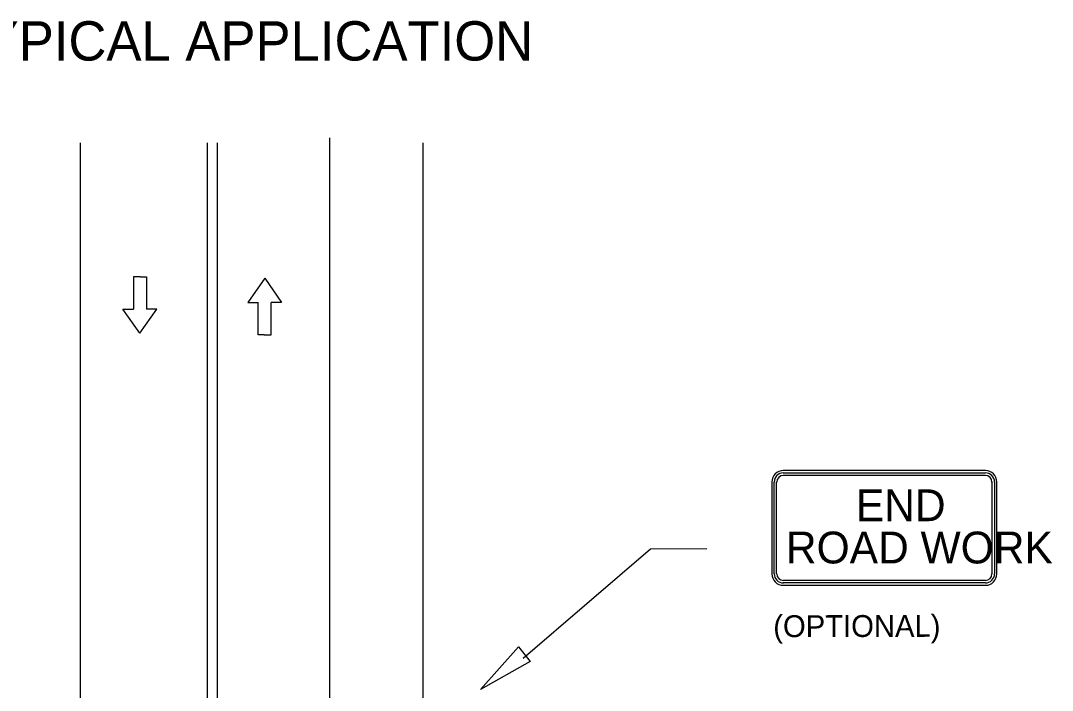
# Model space of a CAD drawing. Extents: x 1531.35 to 1538.58, y 1529.59 to 1539.23.
# Drawn here: x 1535.338 to 1538.171, y 1537.39 to 1539.228 of the extents above; entities that cross this region are included whole.
import ezdxf

# ---------------------------------------------------------------- set-up
doc = ezdxf.new("R2010")
doc.units = 0
for name, color, linetype in [('DETL-DIMS', 7, 'Continuous'), ('DETL-LINE', 7, 'Continuous'), ('DETL-NOTE', 7, 'Continuous'), ('DETL-TITL', 7, 'Continuous'), ('USER-BORD', 7, 'Continuous')]:
    doc.layers.add(name, color=color, linetype=linetype)

# ---------------------------------------------------------------- blocks, each defined once
blk = doc.blocks.new('TD')
at = {"layer": 'USER-BORD'}
for p, q in [((0, 0), (-0.0539, -0.077)), ((0, 0), (0.0539, -0.077)), ((-0.0539, -0.077), (-0.0208, -0.077)), ((-0.0208, -0.1803), (-0.0208, -0.077)), ((0.0208, -0.1803), (0.0208, -0.077)), ((0.0539, -0.077), (0.0208, -0.077)), ((-0.0017, -0.1803), (-0.0208, -0.1803)), ((-0.0017, -0.1803), (0.0017, -0.1803)), ((0.0017, -0.1803), (0.0208, -0.1803))]:
    blk.add_line(p, q, dxfattribs=at)

msp = doc.modelspace()

# ---------------------------------------------------------------- linework, layer by layer
at = {"layer": 'DETL-DIMS'}
for p, q in [((1536.7178, 1537.4779), (1537.0678, 1537.7784)), ((1537.0678, 1537.7784), (1537.2224, 1537.7787))]:
    msp.add_line(p, q, dxfattribs=at)
msp.add_lwpolyline([(1536.7049, 1537.5091), (1536.7372, 1537.4689), (1536.6003, 1537.3919)], close=True, dxfattribs=at)
at = {"layer": 'DETL-LINE'}
for p, q in [((1535.5016, 1538.8924), (1535.5016, 1531.7496)), ((1535.8503, 1538.8924), (1535.8503, 1531.7496)), ((1535.8772, 1538.8924), (1535.8772, 1531.7496)), ((1536.1857, 1538.9058), (1536.1857, 1535.6352)), ((1536.4426, 1538.8924), (1536.4426, 1531.7496)), ((1537.9869, 1537.993), (1537.4322, 1537.993)), ((1537.4322, 1537.9866), (1537.9869, 1537.9866)), ((1537.4008, 1537.9616), (1537.4008, 1537.7094)), ((1537.4072, 1537.7094), (1537.4072, 1537.9616)), ((1537.4139, 1537.7094), (1537.4139, 1537.9616)), ((1537.4322, 1537.9799), (1537.9869, 1537.9799)), ((1538.0049, 1537.9616), (1538.0049, 1537.7094)), ((1538.005, 1537.9614), (1538.0049, 1537.9616)), ((1538.0122, 1537.9616), (1538.0122, 1537.7094)), ((1538.0186, 1537.7094), (1538.0186, 1537.9616)), ((1537.9869, 1537.6914), (1537.4322, 1537.6914)), ((1537.9869, 1537.6842), (1537.4322, 1537.6842)), ((1537.4322, 1537.6778), (1537.9869, 1537.6778))]:
    msp.add_line(p, q, dxfattribs=at)
for centre, radius, start, end in [((1537.4324, 1537.9614), 0.0316, 90, 180), ((1537.4324, 1537.9614), 0.0252, 90, 180), ((1537.987, 1537.9614), 0.0316, 0, 90), ((1537.987, 1537.9614), 0.0252, 0, 90), ((1537.4324, 1537.9614), 0.0181, 90, 180), ((1537.987, 1537.9614), 0.0181, 0, 90), ((1537.4324, 1537.7094), 0.0316, 180, 270), ((1537.4324, 1537.7094), 0.0252, 180, 270), ((1537.4324, 1537.7094), 0.0181, 180, 270), ((1537.987, 1537.7094), 0.0316, 270, 0), ((1537.987, 1537.7094), 0.0181, 270, 0), ((1537.987, 1537.7094), 0.0252, 270, 0)]:
    msp.add_arc(centre, radius, start, end, dxfattribs=at)

# ---------------------------------------------------------------- block references
at = {"layer": 'DETL-LINE', "xscale": 0.8611764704, "yscale": 0.8611764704, "rotation": 180}
msp.add_blockref('TD', (1535.6654, 1538.3696), dxfattribs=at)
at = {"layer": 'DETL-LINE', "xscale": 0.8611764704, "yscale": 0.8611764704}
msp.add_blockref('TD', (1536.0081, 1538.5208), dxfattribs=at)

# ---------------------------------------------------------------- texts
at = {"layer": 'DETL-LINE'}
for s, p in [('END', (1537.6313, 1537.8539)), ('ROAD WORK', (1537.4393, 1537.7379))]:
    msp.add_text(s, height=0.08731, rotation=360, dxfattribs=at).set_placement(p)
at = {"layer": 'DETL-NOTE'}
msp.add_text('(OPTIONAL)', height=0.06, rotation=0.1133, dxfattribs=at).set_placement((1537.4046, 1537.5356))
at = {"layer": 'DETL-TITL'}
msp.add_text('TEMPORARY TRAFFIC CONTROL TYPICAL APPLICATION', height=0.108, dxfattribs=at).set_placement((1532.7973, 1539.1182))

doc.saveas('drawing.dxf')
